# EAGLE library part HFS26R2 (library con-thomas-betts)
THOMAS&BETTS
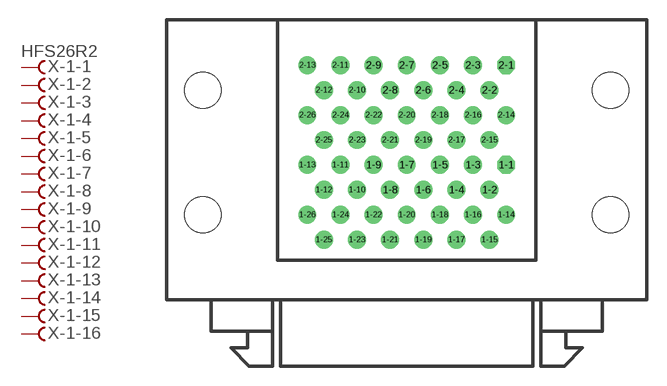
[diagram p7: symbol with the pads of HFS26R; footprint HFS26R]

Designator prefix X; gates -1-1=FV -1-2=F -1-3=F -1-4=F -1-5=F -1-6=F -1-7=F -1-8=F -1-9=F -1-10=F -1-11=F -1-12=F -1-13=F -1-14=F -1-15=F -1-16=F -1-17=F -1-18=F -1-19=F -1-20=F -1-21=F -1-22=F -1-23=F -1-24=F -1-25=F -1-26=F -2-1=FV -2-2=F -2-3=F -2-4=F -2-5=F -2-6=F -2-7=F -2-8=F -2-9=F -2-10=F -2-11=F -2-12=F -2-13=F -2-14=F -2-15=F -2-16=F -2-17=F -2-18=F -2-19=F -2-20=F -2-21=F -2-22=F -2-23=F -2-24=F -2-25=F -2-26=F

## HFS26R2 (OC_FARNELL: unknown; OC_NEWARK: unknown)  [HFS26R]
1-1  -1-1:F  pas
1-2  -1-2:F  pas
1-3  -1-3:F  pas
1-4  -1-4:F  pas
1-5  -1-5:F  pas
1-6  -1-6:F  pas
1-7  -1-7:F  pas
1-8  -1-8:F  pas
1-9  -1-9:F  pas
1-10  -1-10:F  pas
1-11  -1-11:F  pas
1-12  -1-12:F  pas
1-13  -1-13:F  pas
1-14  -1-14:F  pas
1-15  -1-15:F  pas
1-16  -1-16:F  pas
1-17  -1-17:F  pas
1-18  -1-18:F  pas
1-19  -1-19:F  pas
1-20  -1-20:F  pas
1-21  -1-21:F  pas
1-22  -1-22:F  pas
1-23  -1-23:F  pas
1-24  -1-24:F  pas
1-25  -1-25:F  pas
1-26  -1-26:F  pas
2-1  -2-1:F  pas
2-2  -2-2:F  pas
2-3  -2-3:F  pas
2-4  -2-4:F  pas
2-5  -2-5:F  pas
2-6  -2-6:F  pas
2-7  -2-7:F  pas
2-8  -2-8:F  pas
2-9  -2-9:F  pas
2-10  -2-10:F  pas
2-11  -2-11:F  pas
2-12  -2-12:F  pas
2-13  -2-13:F  pas
2-14  -2-14:F  pas
2-15  -2-15:F  pas
2-16  -2-16:F  pas
2-17  -2-17:F  pas
2-18  -2-18:F  pas
2-19  -2-19:F  pas
2-20  -2-20:F  pas
2-21  -2-21:F  pas
2-22  -2-22:F  pas
2-23  -2-23:F  pas
2-24  -2-24:F  pas
2-25  -2-25:F  pas
2-26  -2-26:F  pas

## Footprint HFS26R (pad centres in mm)
THOMAS&BETTS Fine Pitch "D" Connector HFS26Rx29x
drill 0.864 octagon: 1-1 7.62,8.87; 2-1 7.62,16.51
drill 0.864 round: 1-2 6.35,6.96; 1-3 5.08,8.87; 1-4 3.81,6.96; 1-5 2.54,8.87; 1-6 1.27,6.96; 1-7 0,8.87; 1-8 -1.27,6.96; 1-9 -2.54,8.87; 1-10 -3.81,6.96; 1-11 -5.08,8.87; 1-12 -6.35,6.96; 1-13 -7.62,8.87; 1-14 7.62,5.05; 1-15 6.35,3.14; 1-16 5.08,5.05; 1-17 3.81,3.14; 1-18 2.54,5.05; 1-19 1.27,3.14; 1-20 0,5.05; 1-21 -1.27,3.14; 1-22 -2.54,5.05; 1-23 -3.81,3.14; 1-24 -5.08,5.05; 1-25 -6.35,3.14; 1-26 -7.62,5.05; 2-2 6.35,14.6; 2-3 5.08,16.51; 2-4 3.81,14.6; 2-5 2.54,16.51; 2-6 1.27,14.6; 2-7 0,16.51; 2-8 -1.27,14.6; 2-9 -2.54,16.51; 2-10 -3.81,14.6; 2-11 -5.08,16.51; 2-12 -6.35,14.6; 2-13 -7.62,16.51; 2-14 7.62,12.69; 2-15 6.35,10.78; 2-16 5.08,12.69; 2-17 3.81,10.78; 2-18 2.54,12.69; 2-19 1.27,10.78; 2-20 0,12.69; 2-21 -1.27,10.78; 2-22 -2.54,12.69; 2-23 -3.81,10.78; 2-24 -5.08,12.69; 2-25 -6.35,10.78; 2-26 -7.62,12.69
hole 2.769 at 15.621,5.05
hole 2.769 at -15.621,5.05
hole 2.769 at 15.621,14.6
hole 2.769 at -15.621,14.6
